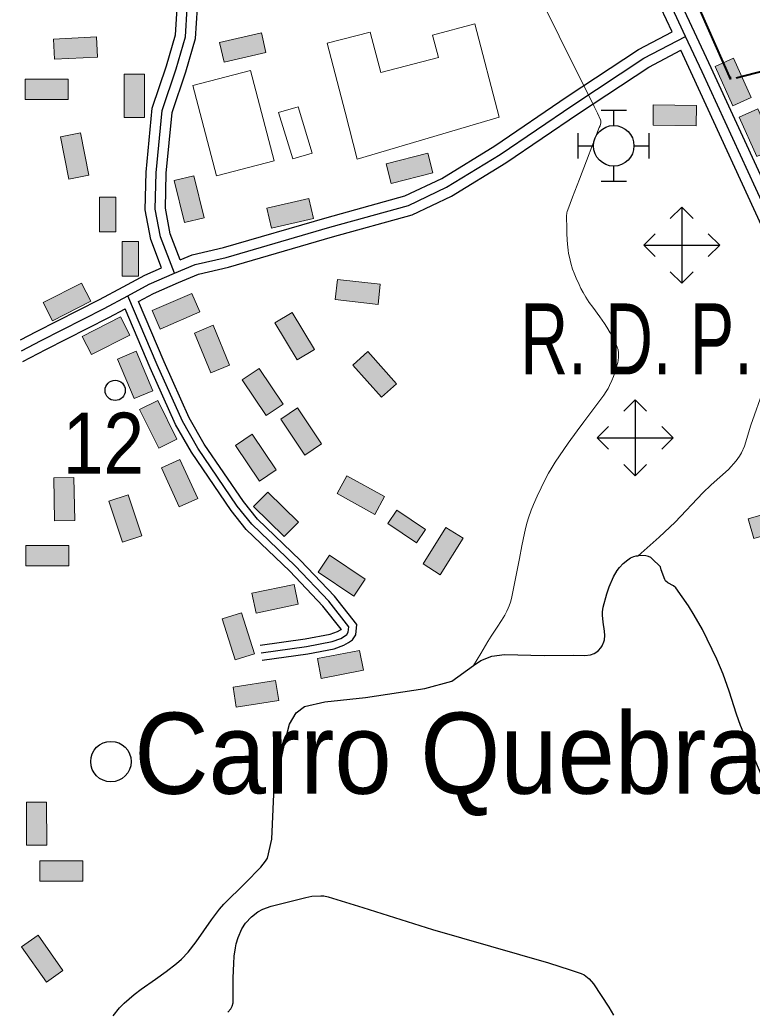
# Model space of a CAD drawing. Extents: x -64005 to -55000, y -89025 to -80000.
# Drawn here: x -64002 to -63279, y -84521 to -83544 of the extents above; entities that cross this region are included whole.
import ezdxf
from ezdxf.enums import TextEntityAlignment as Align

# ---------------------------------------------------------------- set-up
doc = ezdxf.new("R2010")
doc.units = 0
doc.header["$LTSCALE"] = 32
doc.linetypes.add('DOT_DASHED', pattern=[7.7, 5, -1.2, 0.3, -1.2])
doc.linetypes.add('LONG_DASHED', pattern=[7.5, 6, -1.5])
for name, color, linetype, lineweight in [('10', 7, 'Continuous', 25), ('13', 7, 'Continuous', 25), ('16', 7, 'Continuous', 25), ('18', 7, 'Continuous', 25), ('19', 7, 'Continuous', 25), ('2', 7, 'Continuous', 25), ('21', 7, 'Continuous', 25), ('24', 7, 'Continuous', 25), ('39', 7, 'LONG_DASHED', 25), ('52', 7, 'Continuous', 25), ('6', 7, 'Continuous', 25), ('7', 7, 'Continuous', 13)]:
    doc.layers.add(name, color=color, linetype=linetype, lineweight=lineweight)
for name, color, linetype in [('38', 7, 'Continuous'), ('45', 7, 'Continuous'), ('56', 7, 'Continuous')]:
    doc.layers.add(name, color=color, linetype=linetype)

msp = doc.modelspace()

# ---------------------------------------------------------------- hatches: boundary and pattern name
at = {"layer": '7'}
for points in [[(-63926.2, -83561.01), (-63968.65, -83563.12), (-63967.66, -83583.09), (-63925.21, -83580.98)], [(-63763.23, -83556.97), (-63804.64, -83566.53), (-63800.15, -83586.01), (-63758.74, -83576.45)], [(-63315.35, -83590.07), (-63297.96, -83628.85), (-63279.71, -83620.67), (-63297.1, -83581.89)], [(-63898.62, -83597.87), (-63898.62, -83640.37), (-63878.62, -83640.37), (-63878.62, -83597.87)], [(-63953.93, -83602.69), (-63996.43, -83602.69), (-63996.43, -83622.69), (-63953.93, -83622.69)], [(-63376.65, -83648.06), (-63334.15, -83648.7), (-63333.85, -83628.7), (-63376.35, -83628.06)], [(-63291.55, -83640.2), (-63274.15, -83678.97), (-63255.91, -83670.78), (-63273.31, -83632.01)], [(-63961.42, -83659.45), (-63953.29, -83701.17), (-63933.66, -83697.35), (-63941.79, -83655.63)], [(-63598.82, -83675.56), (-63639.99, -83686.08), (-63635.04, -83705.46), (-63593.87, -83694.94)], [(-63849.35, -83702.75), (-63839.3, -83744.04), (-63819.87, -83739.31), (-63829.92, -83698.02)], [(-63906.93, -83753.24), (-63906.93, -83719.24), (-63922.93, -83719.24), (-63922.93, -83753.24)], [(-63716.45, -83720.49), (-63757.86, -83730.06), (-63753.35, -83749.55), (-63711.94, -83739.98)], [(-63884.72, -83796.96), (-63884.72, -83762.96), (-63900.72, -83762.96), (-63900.72, -83796.96)], [(-63940.78, -83803.86), (-63978.69, -83823.08), (-63969.64, -83840.92), (-63931.73, -83821.7)], [(-63690.36, -83820.03), (-63648.14, -83824.9), (-63645.86, -83805.03), (-63688.08, -83800.16)], [(-63831.91, -83813.97), (-63870.95, -83830.75), (-63863.05, -83849.13), (-63824.01, -83832.35)], [(-63749.92, -83843.17), (-63727.93, -83879.54), (-63710.82, -83869.19), (-63732.81, -83832.82)], [(-63902.23, -83837.22), (-63940.12, -83856.45), (-63931.07, -83874.28), (-63893.18, -83855.05)], [(-63794.58, -83884.73), (-63810.89, -83845.48), (-63829.36, -83853.15), (-63813.05, -83892.4)], [(-63905.41, -83878.74), (-63888.7, -83917.82), (-63870.31, -83909.96), (-63887.02, -83870.88)], [(-63673.04, -83884.82), (-63644.71, -83916.5), (-63629.8, -83903.16), (-63658.13, -83871.48)], [(-63741.78, -83923.37), (-63765.48, -83888.1), (-63782.08, -83899.25), (-63758.38, -83934.52)], [(-63883.53, -83928.5), (-63864.65, -83966.57), (-63846.73, -83957.68), (-63865.61, -83919.61)], [(-63703.79, -83962.31), (-63727.49, -83927.04), (-63744.09, -83938.19), (-63720.39, -83973.46)], [(-63748.59, -83988.2), (-63772.29, -83952.93), (-63788.89, -83964.08), (-63765.19, -83999.35)], [(-63862, -83986.06), (-63844.33, -84024.71), (-63826.14, -84016.4), (-63843.81, -83977.75)], [(-63968.26, -83995.84), (-63967.52, -84038.33), (-63947.52, -84037.98), (-63948.26, -83995.49)], [(-63688.58, -84011.55), (-63651.34, -84032.04), (-63641.7, -84014.51), (-63678.94, -83994.02)], [(-63726.65, -84039.67), (-63757.05, -84009.97), (-63771.03, -84024.27), (-63740.63, -84053.97)], [(-63913.75, -84019.05), (-63900.35, -84059.38), (-63881.37, -84053.07), (-63894.77, -84012.74)], [(-63601.2, -84046.85), (-63629.4, -84027.86), (-63638.34, -84041.13), (-63610.14, -84060.12)], [(-63241.8, -84024.67), (-63282.62, -84036.52), (-63277.04, -84055.73), (-63236.22, -84043.88)], [(-63581.12, -84044.89), (-63603.67, -84080.91), (-63586.72, -84091.53), (-63564.17, -84055.51)], [(-63953.3, -84062.8), (-63995.8, -84062.8), (-63995.8, -84082.8), (-63953.3, -84082.8)], [(-63660.79, -84096.02), (-63696.04, -84072.28), (-63707.21, -84088.86), (-63671.96, -84112.6)], [(-63730.98, -84101.12), (-63772.57, -84109.86), (-63768.46, -84129.44), (-63726.87, -84120.7)], [(-63802.08, -84135.04), (-63789.2, -84175.54), (-63770.14, -84169.48), (-63783.02, -84128.98)], [(-63704.24, -84193.75), (-63662.49, -84185.8), (-63666.24, -84166.15), (-63707.99, -84174.1)], [(-63788.11, -84222.33), (-63746.13, -84215.7), (-63749.25, -84195.95), (-63791.23, -84202.58)], [(-63975.22, -84358.27), (-63975.24, -84315.77), (-63995.24, -84315.77), (-63995.22, -84358.27)], [(-63939.53, -84373.84), (-63982.03, -84373.84), (-63982.03, -84393.84), (-63939.53, -84393.84)], [(-63999.96, -84458.72), (-63975.5, -84493.47), (-63959.14, -84481.96), (-63983.6, -84447.21)]]:
    msp.add_hatch(color=256, dxfattribs=at).paths.add_polyline_path(points)

# ---------------------------------------------------------------- linework, layer by layer
at = {"layer": '10'}
msp.add_circle((-63911.74, -84275.88), 20, dxfattribs=at)
at = {"layer": '13'}
msp.add_lwpolyline([(-63684.68, -84145.39), (-63684.3, -84145.12), (-63684.72, -84145.75)], close=True, dxfattribs=at)
at = {"layer": '16'}
for p, q in [((-63427.96, -83633.42), (-63402.96, -83633.42)), ((-63415.46, -83648.42), (-63415.46, -83633.42)), ((-63450.46, -83680.92), (-63450.46, -83655.92)), ((-63380.46, -83680.92), (-63380.46, -83655.92)), ((-63450.46, -83668.42), (-63435.46, -83668.42)), ((-63395.46, -83668.42), (-63380.46, -83668.42)), ((-63415.46, -83703.42), (-63415.46, -83688.42)), ((-63427.96, -83703.42), (-63402.96, -83703.42))]:
    msp.add_line(p, q, dxfattribs=at)
msp.add_circle((-63415.46, -83668.42), 20, dxfattribs=at)
at = {"layer": '18', "linetype": 'DOT_DASHED', "lineweight": 40}
msp.add_lwpolyline([(-62522.87, -83412.36), (-62556.33, -83421.12), (-62591.3, -83430.29), (-62672.42, -83447.92), (-62778.33, -83504.25), (-62909.51, -83489.24), (-63002.04, -83525.29), (-63139.68, -83561.87), (-63299.66, -83603.02), (-63329.94, -83534.65), (-63355.53, -83481.44), (-63385.14, -83439.46), (-63405.52, -83393.25), (-63413.18, -83359.98), (-63529.36, -83399.93), (-63598.11, -83401.99), (-63647.63, -83422.64), (-63678.84, -83450.77)], dxfattribs=at)
at = {"layer": '18'}
msp.add_lwpolyline([(-63310.73, -83578.02), (-63329.94, -83534.65), (-63341.45, -83510.73)], dxfattribs=at)
msp.add_circle((-63300.61, -83600.88), 0.5, dxfattribs=at)
at = {"layer": '19'}
for p, q in [((-63348.31, -83728.94), (-63348.31, -83803.94)), ((-63385.81, -83766.44), (-63310.81, -83766.44)), ((-63394.29, -83918.97), (-63394.29, -83993.97)), ((-63431.79, -83956.47), (-63356.79, -83956.47))]:
    msp.add_line(p, q, dxfattribs=at)
for points in [[(-63337.06, -83740.19), (-63348.31, -83728.94), (-63359.56, -83740.19)], [(-63374.56, -83755.19), (-63385.81, -83766.44), (-63374.56, -83777.69)], [(-63322.06, -83777.69), (-63310.81, -83766.44), (-63322.06, -83755.19)], [(-63359.56, -83792.69), (-63348.31, -83803.94), (-63337.06, -83792.69)], [(-63383.04, -83930.22), (-63394.29, -83918.97), (-63405.54, -83930.22)], [(-63420.54, -83945.22), (-63431.79, -83956.47), (-63420.54, -83967.72)], [(-63368.04, -83967.72), (-63356.79, -83956.47), (-63368.04, -83945.22)], [(-63405.54, -83982.72), (-63394.29, -83993.97), (-63383.04, -83982.72)]]:
    msp.add_lwpolyline(points, dxfattribs=at)
at = {"layer": '2'}
msp.add_line((-63553.71, -84181.23), (-63546.68, -84176.1), dxfattribs=at)
at = {"layer": '2', "lineweight": 13}
for points in [[(-63449.61, -83805.37), (-63452.6, -83798.87), (-63454.61, -83793.89), (-63455.97, -83790.11), (-63457.76, -83784.31), (-63459.23, -83778.38), (-63459.97, -83774.63), (-63460.48, -83771.34), (-63461.13, -83765.58), (-63461.45, -83761.26), (-63461.73, -83754.78), (-63461.86, -83748.3), (-63462.14, -83739.85), (-63462.07, -83737.74), (-63461.7, -83734.61), (-63461.36, -83733.06), (-63460.88, -83731.54), (-63456.26, -83719.23), (-63449.2, -83701.2), (-63442.16, -83683.22), (-63435.9, -83666.87), (-63429.68, -83650.51), (-63428.95, -83648.65), (-63428.45, -83647.2), (-63428.17, -83646.1), (-63428.03, -83644.49), (-63428.13, -83643.7), (-63428.37, -83642.95), (-63431.38, -83636.35), (-63434.61, -83629.8), (-63443.31, -83612.21), (-63452.03, -83594.64), (-63486.37, -83525.79)], [(-63553.71, -84181.23), (-63546.69, -84169.29), (-63539.67, -84157.35), (-63536.47, -84152.18), (-63530.51, -84143.25), (-63526.09, -84136.52), (-63523.01, -84131.38), (-63520.92, -84127.43), (-63519.52, -84124.41), (-63518.57, -84122.11), (-63517.33, -84118.58), (-63516.35, -84114.95), (-63514.23, -84105.11), (-63511.33, -84090.31), (-63508.47, -84075.51), (-63506.02, -84063.02), (-63503.55, -84050.53), (-63502.24, -84044.71), (-63500.87, -84039.67), (-63499.52, -84035.31), (-63496.86, -84027.76), (-63494.64, -84022.17), (-63491.02, -84013.87), (-63487.13, -84005.66), (-63483, -83997.51), (-63479.76, -83991.5), (-63477.23, -83987.07), (-63473.27, -83980.52), (-63469.06, -83974.11), (-63460.43, -83961.72), (-63451.66, -83949.46), (-63445.1, -83940.63), (-63435.02, -83927.57), (-63429.99, -83920.98), (-63425.05, -83914.29), (-63422.75, -83910.85), (-63420.94, -83907.73), (-63419.49, -83904.93), (-63417.23, -83899.89), (-63415.72, -83896.03), (-63413.71, -83890.14), (-63411.91, -83884.21), (-63411.38, -83882.12), (-63411, -83880.25), (-63410.61, -83876.92), (-63410.56, -83874.41), (-63410.68, -83872.53), (-63411.12, -83869.77), (-63411.91, -83867.12), (-63414.06, -83861.99), (-63415.86, -83858.25), (-63418.85, -83852.77), (-63422.1, -83847.4), (-63424.6, -83843.61), (-63429.19, -83837.19), (-63436.2, -83827.71), (-63439.6, -83822.86), (-63442.8, -83817.82), (-63445.51, -83813.15), (-63447.76, -83809.02), (-63449.61, -83805.37)], [(-63391.42, -84072.79), (-63370.64, -84054.59), (-63354.65, -84039.54), (-63327.57, -84010.85), (-63319.31, -84002.96), (-63302.21, -83987.76), (-63294.51, -83979.27), (-63291.12, -83974.55), (-63289.27, -83971.39), (-63286.36, -83964.79), (-63280.14, -83944.05), (-63267.17, -83907.78)]]:
    msp.add_lwpolyline(points, dxfattribs=at)
at = {"layer": '2'}
for points in [[(-63546.68, -84176.1), (-63535.89, -84171.92), (-63523.15, -84170.25), (-63484.13, -84171.05), (-63454.79, -84170.86), (-63443.8, -84171.18), (-63438.38, -84170.53), (-63434.85, -84169.29), (-63433.11, -84168.34), (-63430.56, -84166.42), (-63428.02, -84163.72), (-63426.75, -84161.83), (-63425.07, -84157.86), (-63424.6, -84155.79), (-63424.27, -84151.53), (-63424.52, -84147.14), (-63425.86, -84138.18), (-63426.62, -84131.52), (-63426.63, -84128.28), (-63425.91, -84123.58), (-63422.12, -84110.23), (-63419.9, -84103.6), (-63415.68, -84093.77), (-63411.91, -84087.29), (-63409.74, -84084.37), (-63405.97, -84080.35), (-63401.45, -84076.7), (-63398.86, -84075), (-63395.54, -84073.47), (-63393.33, -84072.92), (-63391.42, -84072.79)], [(-63268.99, -84290.75), (-63290.21, -84240.26), (-63294.36, -84229.15), (-63301.53, -84206.51), (-63307.32, -84189.65), (-63313.62, -84174.76), (-63327.91, -84145.69), (-63335.85, -84131.44), (-63341.64, -84122.27), (-63354.01, -84104.48), (-63356.28, -84102.45), (-63362, -84099.52), (-63364.3, -84097.62), (-63365.07, -84096.35), (-63368.43, -84086.74), (-63369.33, -84083.74), (-63377.75, -84075.4), (-63378.73, -84074.6), (-63381.02, -84073.49), (-63383.62, -84072.91), (-63388.9, -84072.61), (-63391.42, -84072.79)], [(-63752.81, -84352.52), (-63750.92, -84307.97), (-63739.86, -84255.3), (-63735.51, -84238.81), (-63729.07, -84227.82), (-63720.54, -84221.56), (-63700.72, -84216.88), (-63660.56, -84212.7), (-63601.82, -84203.6), (-63575.3, -84196.39), (-63553.71, -84181.23)], [(-63909.48, -84526.69), (-63903.44, -84518.9), (-63898.85, -84514.15), (-63888.97, -84505.54), (-63882.03, -84500.28), (-63867.75, -84490.37), (-63857.14, -84482.96), (-63847, -84475.09), (-63842.23, -84470.84), (-63835.57, -84463.94), (-63827.49, -84453.62), (-63812.58, -84431.81), (-63804.61, -84421.34), (-63800.25, -84416.44), (-63779.22, -84395.76), (-63763.65, -84379.99), (-63759.21, -84374.19), (-63757.32, -84371.06), (-63752.81, -84352.52)]]:
    msp.add_lwpolyline(points, dxfattribs=at)
at = {"layer": '21'}
for points in [[(-63762.59, -84175.86), (-63717.54, -84169.68), (-63691.36, -84164.69), (-63681.74, -84161.16), (-63677.14, -84158.42), (-63673.38, -84155.8), (-63670.14, -84150.93), (-63669.15, -84140.56), (-63691.12, -84112.77), (-63724.66, -84077.59), (-63767.13, -84036.73), (-63781.07, -84019.38), (-63819.62, -83962.73), (-63834.54, -83936.64), (-63859.39, -83881.55), (-63884.46, -83821.95)], [(-63684.68, -84145.39), (-63684.65, -84145.12), (-63702.46, -84122.61), (-63735.3, -84088.17), (-63778.23, -84046.87), (-63793.13, -84028.3), (-63832.36, -83970.69), (-63847.92, -83943.46), (-63873.15, -83887.55), (-63897.72, -83829.1)], [(-63764.63, -84161), (-63719.96, -84154.88), (-63695.38, -84150.19), (-63688.22, -84147.56), (-63685.28, -84145.8), (-63684.68, -84145.39)]]:
    msp.add_lwpolyline(points, dxfattribs=at)
at = {"layer": '24'}
msp.add_lwpolyline([(-63796.47, -84522.95), (-63793.55, -84519.68), (-63792.16, -84517.24), (-63791.28, -84513.88), (-63791, -84505.69), (-63791.28, -84489.32), (-63790.58, -84475.05), (-63790.02, -84467.91), (-63788.91, -84459.58), (-63788.06, -84455.48), (-63786.33, -84449.46), (-63782.45, -84440.78), (-63778.86, -84435.3), (-63773.02, -84428.87), (-63766.84, -84424.09), (-63761.71, -84421.3), (-63753.76, -84418.35), (-63719.37, -84409.77), (-63713.44, -84408.66), (-63704.64, -84408.17), (-63701.75, -84408.43), (-63697.46, -84409.33), (-63663.01, -84419.74), (-63594.2, -84441.43), (-63479.96, -84474.33), (-63458.28, -84481.21), (-63447.47, -84484.86), (-63444.56, -84486.16), (-63439.54, -84490.01), (-63435.31, -84495.04), (-63420.34, -84518.06), (-63415.56, -84526.01)], dxfattribs=at)
at = {"layer": '39', "linetype": 'Continuous'}
for points in [[(-63848.98, -83794.2), (-63862.85, -83758.11), (-63867.98, -83730.79), (-63867.12, -83694.92), (-63861.16, -83633.43), (-63847.5, -83592.45), (-63838.11, -83560.84), (-63836.41, -83532.66), (-63843.23, -83482.28), (-63852.62, -83391.76), (-63867.99, -83358.47), (-63888.47, -83319.19), (-63898.71, -83308.09), (-63903.83, -83307.23), (-63913.22, -83311.51), (-63930.29, -83320.9), (-63945.65, -83326.03), (-63963.59, -83329.44), (-63978.1, -83329.45), (-63994.31, -83321.77), (-64000, -83316.07)], [(-63344.61, -83560.52), (-63359.78, -83528.12), (-63375.9, -83493.34), (-63390.41, -83471.14), (-63413.45, -83438.69), (-63425.4, -83406.25), (-63429.27, -83389.92)], [(-63848.98, -83794.2), (-63828.52, -83785.4), (-63798.1, -83778.5), (-63695.68, -83748.61), (-63618.01, -83727.25), (-63580.45, -83709.31), (-63527.53, -83676.85), (-63455.83, -83628.17), (-63385.83, -83582.05), (-63344.61, -83560.52)], [(-63247.07, -83776.7), (-63252.52, -83759.8), (-63328.2, -83595.58), (-63344.61, -83560.52)], [(-63894.98, -83816.26), (-63874.07, -83804.99), (-63848.98, -83794.2)], [(-64000, -83870.61), (-63980.76, -83860.51), (-63918.45, -83828.9), (-63894.98, -83816.26)]]:
    msp.add_lwpolyline(points, dxfattribs=at)
at = {"layer": '39', "linetype": 'DOT_DASHED'}
msp.add_lwpolyline([(-63763.61, -84168.43), (-63718.75, -84162.28), (-63693.37, -84157.44), (-63684.98, -84154.36), (-63681.21, -84152.11), (-63678.84, -84150.46), (-63677.43, -84148.34), (-63676.9, -84142.84), (-63696.79, -84117.69), (-63729.98, -84082.88), (-63772.68, -84041.8), (-63787.1, -84023.84), (-63825.99, -83966.71), (-63841.23, -83940.05), (-63866.27, -83884.55), (-63894.98, -83816.26)], dxfattribs=at)
at = {"layer": '52'}
msp.add_circle((-63907.61, -83909.67), 10, dxfattribs=at)
at = {"layer": '6'}
for points in [[(-63335.56, -83556.28), (-63350.71, -83523.89), (-63367.13, -83488.47), (-63382.14, -83465.51), (-63404.53, -83433.98), (-63415.81, -83403.36), (-63419.54, -83387.61), (-63427.78, -83352.91), (-63441.85, -83315.96), (-63465.16, -83274.51), (-63475.96, -83253.27)], [(-63843.38, -83780.9), (-63853.18, -83755.38), (-63857.95, -83729.98), (-63857.13, -83695.52), (-63851.32, -83635.52), (-63837.97, -83595.45), (-63828.2, -83562.59), (-63826.37, -83532.29), (-63833.3, -83481.09), (-63842.85, -83389.08), (-63859.02, -83354.06), (-63880.22, -83313.39), (-63893.68, -83298.8), (-63905.19, -83296.86), (-63917.71, -83302.56), (-63934.32, -83311.7), (-63948.18, -83316.34), (-63964.54, -83319.44), (-63975.86, -83319.45), (-63988.46, -83313.48), (-63998.23, -83303.68)], [(-63861.77, -83788.81), (-63872.52, -83760.84), (-63878.01, -83731.6), (-63877.11, -83694.32), (-63871, -83631.34), (-63857.03, -83589.45), (-63848.02, -83559.09), (-63846.45, -83533.03), (-63853.16, -83483.47), (-63862.39, -83394.44), (-63876.96, -83362.88), (-63896.72, -83324.99), (-63903.22, -83317.94), (-63908.73, -83320.46), (-63926.26, -83330.1), (-63943.12, -83335.72), (-63962.64, -83339.44), (-63980.34, -83339.45), (-64000.16, -83330.06), (-64001.77, -83328.46)], [(-63357.73, -83556.09), (-63368.85, -83532.35), (-63384.67, -83498.21), (-63398.68, -83476.77), (-63422.37, -83443.4), (-63438, -83400.96)], [(-63843.38, -83780.9), (-63831.63, -83775.85), (-63800.61, -83768.82), (-63698.41, -83738.98), (-63621.52, -83717.85), (-63585.24, -83700.51), (-63532.96, -83668.45), (-63461.39, -83619.86), (-63390.91, -83573.42), (-63357.73, -83556.09)], [(-63234.37, -83783.49), (-63240.52, -83764.43), (-63243.19, -83756.16), (-63319.13, -83591.37), (-63335.56, -83556.28)], [(-63845.03, -83803.39), (-63825.41, -83794.95), (-63795.59, -83788.18), (-63692.95, -83758.24), (-63614.5, -83736.65), (-63575.66, -83718.11), (-63522.1, -83685.25), (-63450.27, -83636.48), (-63380.75, -83590.68), (-63349.23, -83574.22)], [(-63107.41, -84490.28), (-63110.95, -84476.01), (-63120.67, -84408.65), (-63130.31, -84325.27), (-63145.35, -84196.38), (-63164.03, -84076.77), (-63173.59, -84037.13), (-63180.14, -84009.95), (-63197.82, -83961.96), (-63256.59, -83779.77), (-63261.85, -83763.44), (-63337.27, -83599.79), (-63349.23, -83574.22)], [(-63899.73, -83807.46), (-63878.43, -83795.98), (-63861.77, -83788.81)], [(-63884.46, -83821.95), (-63869.71, -83814), (-63845.03, -83803.39)], [(-64001.16, -83859.93), (-63985.35, -83851.63), (-63923.09, -83820.03), (-63899.72, -83807.46)], [(-63998.84, -83881.29), (-63976.17, -83869.39), (-63913.81, -83837.77), (-63897.72, -83829.1)]]:
    msp.add_lwpolyline(points, dxfattribs=at)
at = {"layer": '7'}
for points in [[(-63698.27, -83567.31), (-63680.5, -83635.33), (-63668.74, -83681.71), (-63528.56, -83640.31), (-63552.66, -83548.23), (-63594.29, -83559.12), (-63588.47, -83581.21), (-63645.41, -83596.1), (-63655.83, -83556.21)], [(-63926.2, -83561.01), (-63968.65, -83563.12), (-63967.66, -83583.09), (-63925.21, -83580.98)], [(-63763.23, -83556.97), (-63804.64, -83566.53), (-63800.15, -83586.01), (-63758.74, -83576.45)], [(-63315.35, -83590.07), (-63297.96, -83628.85), (-63279.71, -83620.67), (-63297.1, -83581.89)], [(-63898.62, -83597.87), (-63898.62, -83640.37), (-63878.62, -83640.37), (-63878.62, -83597.87)], [(-63773.98, -83594.12), (-63750.64, -83683.14), (-63807.61, -83698.08), (-63830.95, -83609.06)], [(-63953.93, -83602.69), (-63996.43, -83602.69), (-63996.43, -83622.69), (-63953.93, -83622.69)], [(-63376.65, -83648.06), (-63334.15, -83648.7), (-63333.85, -83628.7), (-63376.35, -83628.06)], [(-63746.27, -83635.54), (-63732.34, -83681.12), (-63713.13, -83675.51), (-63727.06, -83629.93)], [(-63291.55, -83640.2), (-63274.15, -83678.97), (-63255.91, -83670.78), (-63273.31, -83632.01)], [(-63961.42, -83659.45), (-63953.29, -83701.17), (-63933.66, -83697.35), (-63941.79, -83655.63)], [(-63598.82, -83675.56), (-63639.99, -83686.08), (-63635.04, -83705.46), (-63593.87, -83694.94)], [(-63849.35, -83702.75), (-63839.3, -83744.04), (-63819.87, -83739.31), (-63829.92, -83698.02)], [(-63906.93, -83753.24), (-63906.93, -83719.24), (-63922.93, -83719.24), (-63922.93, -83753.24)], [(-63716.45, -83720.49), (-63757.86, -83730.06), (-63753.35, -83749.55), (-63711.94, -83739.98)], [(-63884.72, -83796.96), (-63884.72, -83762.96), (-63900.72, -83762.96), (-63900.72, -83796.96)], [(-63940.78, -83803.86), (-63978.69, -83823.08), (-63969.64, -83840.92), (-63931.73, -83821.7)], [(-63690.36, -83820.03), (-63648.14, -83824.9), (-63645.86, -83805.03), (-63688.08, -83800.16)], [(-63831.91, -83813.97), (-63870.95, -83830.75), (-63863.05, -83849.13), (-63824.01, -83832.35)], [(-63749.92, -83843.17), (-63727.93, -83879.54), (-63710.82, -83869.19), (-63732.81, -83832.82)], [(-63902.23, -83837.22), (-63940.12, -83856.45), (-63931.07, -83874.28), (-63893.18, -83855.05)], [(-63794.58, -83884.73), (-63810.89, -83845.48), (-63829.36, -83853.15), (-63813.05, -83892.4)], [(-63905.41, -83878.74), (-63888.7, -83917.82), (-63870.31, -83909.96), (-63887.02, -83870.88)], [(-63673.04, -83884.82), (-63644.71, -83916.5), (-63629.8, -83903.16), (-63658.13, -83871.48)], [(-63741.78, -83923.37), (-63765.48, -83888.1), (-63782.08, -83899.25), (-63758.38, -83934.52)], [(-63883.53, -83928.5), (-63864.65, -83966.57), (-63846.73, -83957.68), (-63865.61, -83919.61)], [(-63703.79, -83962.31), (-63727.49, -83927.04), (-63744.09, -83938.19), (-63720.39, -83973.46)], [(-63748.59, -83988.2), (-63772.29, -83952.93), (-63788.89, -83964.08), (-63765.19, -83999.35)], [(-63862, -83986.06), (-63844.33, -84024.71), (-63826.14, -84016.4), (-63843.81, -83977.75)], [(-63968.26, -83995.84), (-63967.52, -84038.33), (-63947.52, -84037.98), (-63948.26, -83995.49)], [(-63688.58, -84011.55), (-63651.34, -84032.04), (-63641.7, -84014.51), (-63678.94, -83994.02)], [(-63726.65, -84039.67), (-63757.05, -84009.97), (-63771.03, -84024.27), (-63740.63, -84053.97)], [(-63913.75, -84019.05), (-63900.35, -84059.38), (-63881.37, -84053.07), (-63894.77, -84012.74)], [(-63601.2, -84046.85), (-63629.4, -84027.86), (-63638.34, -84041.13), (-63610.14, -84060.12)], [(-63241.8, -84024.67), (-63282.62, -84036.52), (-63277.04, -84055.73), (-63236.22, -84043.88)], [(-63581.12, -84044.89), (-63603.67, -84080.91), (-63586.72, -84091.53), (-63564.17, -84055.51)], [(-63953.3, -84062.8), (-63995.8, -84062.8), (-63995.8, -84082.8), (-63953.3, -84082.8)], [(-63660.79, -84096.02), (-63696.04, -84072.28), (-63707.21, -84088.86), (-63671.96, -84112.6)], [(-63730.98, -84101.12), (-63772.57, -84109.86), (-63768.46, -84129.44), (-63726.87, -84120.7)], [(-63802.08, -84135.04), (-63789.2, -84175.54), (-63770.14, -84169.48), (-63783.02, -84128.98)], [(-63704.24, -84193.75), (-63662.49, -84185.8), (-63666.24, -84166.15), (-63707.99, -84174.1)], [(-63788.11, -84222.33), (-63746.13, -84215.7), (-63749.25, -84195.95), (-63791.23, -84202.58)], [(-63975.22, -84358.27), (-63975.24, -84315.77), (-63995.24, -84315.77), (-63995.22, -84358.27)], [(-63939.53, -84373.84), (-63982.03, -84373.84), (-63982.03, -84393.84), (-63939.53, -84393.84)], [(-63999.96, -84458.72), (-63975.5, -84493.47), (-63959.14, -84481.96), (-63983.6, -84447.21)]]:
    msp.add_lwpolyline(points, close=True, dxfattribs=at)

# ---------------------------------------------------------------- texts
at = {"layer": '38', "width": 0.9}
msp.add_text('12', height=60, rotation=0.008, dxfattribs=at).set_placement((-63919.2, -83991.68), align=Align.CENTER)
at = {"layer": '45', "width": 0.95}
msp.add_text('Carro Quebrado', height=80, rotation=0.008, dxfattribs=at).set_placement((-63521.59, -84307.55), align=Align.CENTER)
at = {"layer": '56', "width": 0.7}
msp.add_text('R. D. P.', height=70, dxfattribs=at).set_placement((-63507.71, -83893.9))

doc.saveas('drawing.dxf')
